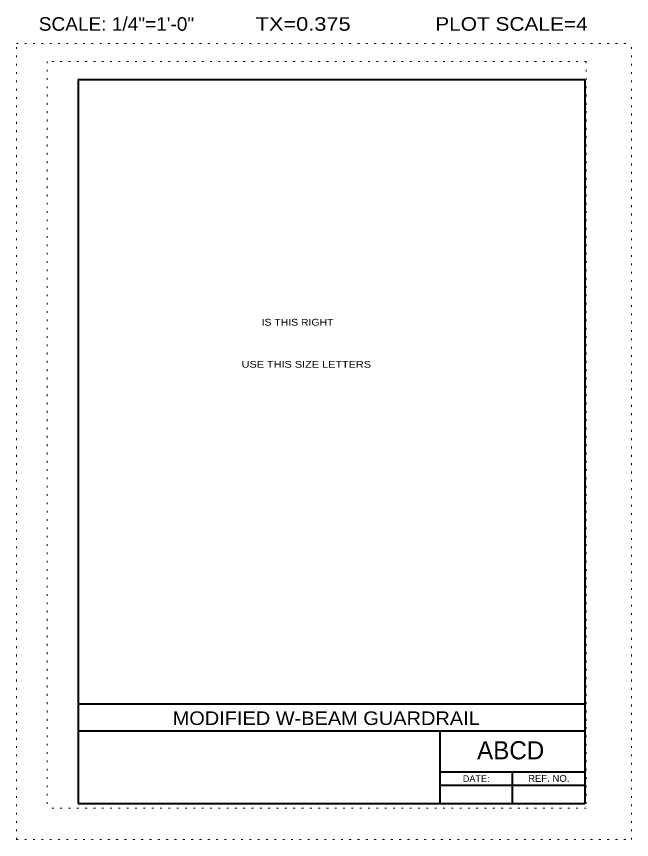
# Model space of a CAD drawing. Extents: x 1370 to 1404, y -905.5 to -860.
import ezdxf
from ezdxf.enums import TextEntityAlignment as Align

# ---------------------------------------------------------------- set-up
doc = ezdxf.new("R2010")
doc.units = 0
doc.header["$LTSCALE"] = 0.3
doc.linetypes.add('DOTTED', pattern=[1.5, 0.3, -1.2])
for name, color, linetype in [('57', 7, 'Continuous'), ('59', 7, 'Continuous'), ('8', 7, 'Continuous'), ('9', 7, 'Continuous')]:
    doc.layers.add(name, color=color, linetype=linetype)
for name, color, linetype, lineweight in [('61', 7, 'DOTTED', 13), ('62', 7, 'DOTTED', 13), ('63', 7, 'Continuous', 40)]:
    doc.layers.add(name, color=color, linetype=linetype, lineweight=lineweight)

msp = doc.modelspace()

# ---------------------------------------------------------------- linework, layer by layer
at = {"layer": '61'}
for p, q in [((1401.5, -862.49), (1371.7, -862.49)), ((1371.7, -862.49), (1371.7, -903.76)), ((1401.5, -862.49), (1401.5, -903.76)), ((1401.5, -903.76), (1371.7, -903.76))]:
    msp.add_line(p, q, dxfattribs=at)
at = {"layer": '62'}
for p, q in [((1370, -905.5), (1370, -861.5)), ((1370, -861.5), (1404, -861.5)), ((1404, -905.5), (1404, -861.5)), ((1370, -905.5), (1404, -905.5))]:
    msp.add_line(p, q, dxfattribs=at)
at = {"layer": '63'}
for p, q in [((1373.4167, -863.5), (1373.4167, -903.5)), ((1373.4167, -863.5), (1401.4167, -863.5)), ((1401.4167, -863.5), (1401.4167, -903.5)), ((1373.4167, -898), (1401.4167, -898)), ((1373.4167, -899.5), (1401.4167, -899.5)), ((1393.4167, -903.5), (1393.4167, -899.5)), ((1393.4167, -901.75), (1401.4167, -901.75)), ((1397.4167, -903.5), (1397.4167, -901.75)), ((1393.4167, -902.5), (1401.4167, -902.5)), ((1373.4167, -903.5), (1401.4167, -903.5))]:
    msp.add_line(p, q, dxfattribs=at)

# ---------------------------------------------------------------- texts
at = {"layer": '57', "width": 1.1}
msp.add_text('MODIFIED W-BEAM GUARDRAIL', height=0.75, dxfattribs=at).set_placement((1378.6328, -899.1685))
at = {"layer": '57'}
msp.add_text('ABCD', height=1, dxfattribs=at).set_placement((1395.4602, -901.066))
at = {"layer": '59'}
msp.add_text('DATE:', height=0.3753, dxfattribs=at).set_placement((1395.4115, -902.3243), align=Align.CENTER)
at = {"layer": '59', "width": 1.05}
msp.add_text('REF. NO.', height=0.3753, dxfattribs=at).set_placement((1399.4242, -902.311), align=Align.CENTER)
at = {"layer": '8'}
for s, width, p in [('IS THIS RIGHT', 1.15, (1383.5492, -877.0969)), ('USE THIS SIZE LETTERS', 1.2, (1382.4448, -879.422))]:
    msp.add_text(s, height=0.375, dxfattribs=dict(at, width=width)).set_placement(p)
at = {"layer": '9'}
for s, width, p in [('SCALE: 1/4"=1\'-0"', 1.05, (1375.5273, -860.7977)), ('TX=0.375', 1.2, (1385.8466, -860.7977)), ('PLOT SCALE=4', 1.15, (1397.3626, -860.7977))]:
    msp.add_text(s, height=0.75, dxfattribs=dict(at, width=width)).set_placement(p, align=Align.CENTER)

doc.saveas('drawing.dxf')
